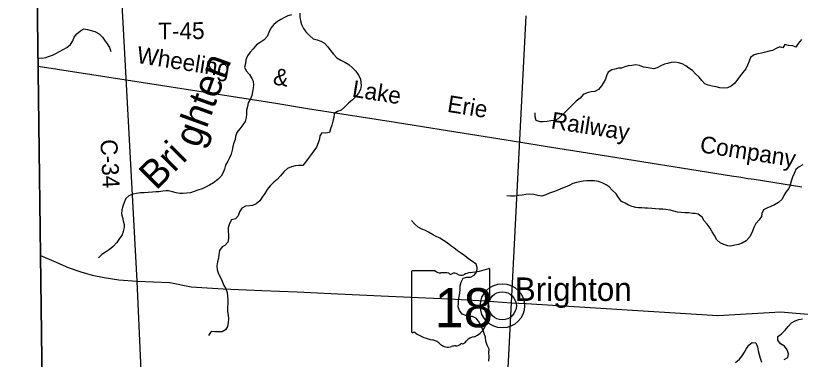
# Model space of a CAD drawing. Extents: x 1857828 to 2277390, y 930619 to 1324581.
# Drawn here: x 2012264 to 2026202, y 1154192 to 1160303 of the extents above; entities that cross this region are included whole.
import ezdxf

# ---------------------------------------------------------------- set-up
doc = ezdxf.new("R2010")
doc.units = 0
for name, color, linetype in [('GM_X_Adjacent_County', 7, 'Continuous'), ('GM_X_County', 7, 'Continuous'), ('GM_X_County_Road', 7, 'Continuous'), ('GM_X_County_Road_Text', 7, 'Continuous'), ('GM_X_Major_River', 7, 'Continuous'), ('GM_X_Minor_River', 7, 'Continuous'), ('GM_X_Minor_River_Text', 7, 'Continuous'), ('GM_X_Rail_Line', 7, 'Continuous'), ('GM_X_Rail_Line_Text', 7, 'Continuous'), ('GM_X_State_Location', 7, 'Continuous'), ('GM_X_State_Route', 7, 'Continuous'), ('GM_X_State_Shield', 7, 'Continuous'), ('GM_X_Township', 7, 'Continuous'), ('GM_X_Township_Road_Text', 7, 'Continuous'), ('GM_X_Unincorporated', 7, 'Continuous'), ('GM_X_Unincorporated_Location', 7, 'Continuous'), ('GM_X_Unincorporated_Text', 7, 'Continuous')]:
    doc.layers.add(name, color=color, linetype=linetype)

msp = doc.modelspace()

# ---------------------------------------------------------------- linework, layer by layer
at = {"layer": 'GM_X_Adjacent_County'}
msp.add_lwpolyline([(2012647, 1160718), (2012707, 1156038), (2012755, 1152350), (2012777, 1149904), (2012943, 1143096), (2013016, 1137995), (2013087, 1135030), (2013201, 1130286), (2013424, 1120950), (2013523, 1116786), (2010804, 1116774), (2007584, 1116766), (2002726, 1116787), (1997008, 1116752)], dxfattribs=at)
at = {"layer": 'GM_X_County'}
msp.add_lwpolyline([(2027656, 1116790), (2024866, 1116799), (2023245, 1116823), (2022479, 1116818), (2021874, 1116815), (2020156, 1116833), (2016220, 1116802), (2013523, 1116786), (2013424, 1120950), (2013201, 1130286), (2013087, 1135030), (2013016, 1137995), (2012943, 1143096), (2012777, 1149904), (2012755, 1152350), (2012707, 1156038), (2012647, 1160718)], dxfattribs=at)
at = {"layer": 'GM_X_County_Road'}
for points in [[(2014423, 1155583), (2014164, 1160397), (2013943, 1164756), (2013892, 1166007)], [(2014989, 1143103), (2014948, 1143924), (2014904, 1144864), (2014423, 1155583)]]:
    msp.add_lwpolyline(points, dxfattribs=at)
at = {"layer": 'GM_X_Major_River'}
for points in [[(2025913, 1154187), (2025978, 1154222), (2025993, 1154292), (2025968, 1154359), (2025921, 1154426), (2025853, 1154467), (2025800, 1154532), (2025802, 1154598), (2025869, 1154644), (2025931, 1154711), (2025988, 1154774), (2026043, 1154838), (2026112, 1154877), (2026175, 1154898), (2026243, 1154911)], [(2025048, 1154136), (2025121, 1154193), (2025171, 1154255), (2025208, 1154316), (2025245, 1154384), (2025286, 1154444), (2025347, 1154491), (2025411, 1154484), (2025440, 1154411), (2025455, 1154343), (2025474, 1154276), (2025486, 1154212), (2025513, 1154143)]]:
    msp.add_lwpolyline(points, dxfattribs=at)
at = {"layer": 'GM_X_Minor_River'}
for points in [[(2017311, 1160348), (2017314, 1160282), (2017323, 1160211), (2017339, 1160147), (2017374, 1160078), (2017421, 1160015), (2017482, 1159948), (2017548, 1159893), (2017620, 1159872), (2017684, 1159853), (2017752, 1159815), (2017809, 1159752), (2017855, 1159685), (2017910, 1159616), (2017967, 1159553), (2018037, 1159510), (2018109, 1159479), (2018179, 1159438), (2018246, 1159378), (2018306, 1159315), (2018355, 1159248), (2018390, 1159179), (2018398, 1159113), (2018399, 1159063), (2018388, 1158991), (2018355, 1158923), (2018306, 1158864), (2018247, 1158804), (2018177, 1158745), (2018106, 1158674), (2018043, 1158623), (2017980, 1158600), (2017920, 1158566), (2017913, 1158492), (2017900, 1158428), (2017879, 1158358), (2017859, 1158290), (2017838, 1158226), (2017770, 1158213), (2017702, 1158218), (2017667, 1158165), (2017660, 1158111), (2017637, 1158039), (2017610, 1157967), (2017559, 1157897), (2017515, 1157836), (2017462, 1157766), (2017415, 1157701), (2017364, 1157641), (2017292, 1157636), (2017227, 1157635), (2017161, 1157618), (2017094, 1157583), (2017027, 1157524), (2016969, 1157457), (2016908, 1157391), (2016849, 1157340), (2016786, 1157275), (2016729, 1157211), (2016688, 1157138), (2016643, 1157078), (2016601, 1157011), (2016536, 1156955), (2016472, 1156930), (2016417, 1156921), (2016349, 1156916), (2016280, 1156879), (2016241, 1156813), (2016214, 1156745), (2016171, 1156688), (2016098, 1156671), (2016061, 1156607), (2016040, 1156533), (2016041, 1156461), (2016044, 1156411), (2016047, 1156343), (2016034, 1156274)], [(2017162, 1160316), (2017101, 1160299), (2017039, 1160270), (2016976, 1160233), (2016913, 1160200), (2016850, 1160144), (2016795, 1160079), (2016760, 1160005), (2016733, 1159935), (2016679, 1159874), (2016608, 1159829), (2016541, 1159784), (2016482, 1159716), (2016431, 1159653), (2016380, 1159587), (2016355, 1159520), (2016344, 1159451), (2016331, 1159387), (2016356, 1159323), (2016416, 1159260), (2016461, 1159189), (2016482, 1159138), (2016487, 1159070), (2016483, 1159018), (2016472, 1158948), (2016459, 1158886), (2016438, 1158822), (2016393, 1158756), (2016384, 1158688), (2016367, 1158622), (2016366, 1158554), (2016357, 1158490), (2016338, 1158422), (2016297, 1158360), (2016243, 1158289), (2016194, 1158223), (2016171, 1158153), (2016160, 1158103), (2016137, 1158043), (2016122, 1157975), (2016111, 1157913), (2016092, 1157839), (2016065, 1157778), (2016030, 1157714), (2015993, 1157644), (2015974, 1157574), (2015947, 1157512), (2015912, 1157451), (2015855, 1157387), (2015780, 1157332), (2015709, 1157291), (2015646, 1157258), (2015577, 1157225), (2015502, 1157200), (2015436, 1157175), (2015371, 1157154), (2015305, 1157145), (2015236, 1157138), (2015182, 1157141), (2015116, 1157152), (2015050, 1157169), (2014980, 1157188), (2014929, 1157189), (2014879, 1157181), (2014805, 1157172), (2014752, 1157169), (2014692, 1157166), (2014619, 1157159), (2014547, 1157154), (2014479, 1157151), (2014410, 1157142), (2014344, 1157127), (2014275, 1157102), (2014220, 1157049), (2014193, 1156981), (2014168, 1156915), (2014151, 1156849), (2014146, 1156781), (2014161, 1156716), (2014174, 1156654), (2014191, 1156588), (2014191, 1156537), (2014176, 1156467), (2014153, 1156403), (2014106, 1156338), (2014060, 1156272), (2013997, 1156201), (2013930, 1156146), (2013861, 1156099), (2013796, 1156054), (2013733, 1155998)], [(2012666, 1159555), (2012733, 1159546), (2012797, 1159562), (2012848, 1159577), (2012915, 1159604), (2012979, 1159633), (2013109, 1159703), (2013174, 1159740), (2013237, 1159792), (2013280, 1159855), (2013305, 1159923), (2013350, 1159983), (2013413, 1160032), (2013468, 1160069), (2013538, 1160058), (2013606, 1160039), (2013672, 1160020), (2013746, 1159981), (2013808, 1159922), (2013853, 1159853), (2013886, 1159802), (2013932, 1159737), (2013957, 1159668)], [(2026224, 1159878), (2026166, 1159806), (2026121, 1159745), (2026067, 1159766), (2025995, 1159775), (2025929, 1159788), (2025894, 1159734), (2025840, 1159751), (2025775, 1159718), (2025710, 1159683), (2025646, 1159670), (2025583, 1159656), (2025515, 1159635), (2025450, 1159626), (2025384, 1159609), (2025319, 1159562), (2025292, 1159496), (2025261, 1159424), (2025234, 1159357), (2025182, 1159295), (2025133, 1159234), (2025086, 1159168), (2025037, 1159105), (2024974, 1159051), (2024909, 1159020), (2024845, 1159017), (2024773, 1159020), (2024706, 1159035), (2024636, 1159051), (2024568, 1159068), (2024504, 1159091), (2024451, 1159150), (2024403, 1159211), (2024342, 1159268), (2024288, 1159327)], [(2024288, 1159327), (2024221, 1159368), (2024169, 1159411), (2024103, 1159448), (2024039, 1159467), (2023975, 1159478), (2023906, 1159469), (2023840, 1159454), (2023789, 1159439), (2023725, 1159410), (2023660, 1159374), (2023597, 1159359), (2023533, 1159368), (2023465, 1159383), (2023415, 1159386), (2023347, 1159419), (2023283, 1159432), (2023212, 1159417), (2023146, 1159410), (2023083, 1159393), (2023023, 1159372), (2022972, 1159367), (2022906, 1159354), (2022855, 1159343), (2022788, 1159301), (2022759, 1159234), (2022742, 1159172), (2022697, 1159106), (2022668, 1159054), (2022617, 1158993), (2022552, 1158952), (2022486, 1158947), (2022413, 1158934), (2022347, 1158901), (2022289, 1158835), (2022218, 1158780), (2022155, 1158717), (2022025, 1158590), (2021966, 1158535), (2021908, 1158472), (2021840, 1158441), (2021771, 1158434), (2021707, 1158421), (2021630, 1158418), (2021578, 1158414), (2021512, 1158440), (2021493, 1158506), (2021492, 1158578)], [(2026249, 1157649), (2026182, 1157614), (2026123, 1157567), (2026094, 1157499), (2026061, 1157433), (2026038, 1157361), (2026021, 1157295), (2025998, 1157229), (2025947, 1157166), (2025912, 1157104), (2025879, 1157042), (2025816, 1156979), (2025745, 1156940), (2025676, 1156911), (2025609, 1156882), (2025546, 1156851), (2025521, 1156783), (2025513, 1156733), (2025469, 1156671), (2025410, 1156610), (2025379, 1156536), (2025352, 1156470), (2025327, 1156416), (2025298, 1156363), (2025243, 1156299), (2025170, 1156258), (2025106, 1156235), (2025037, 1156220), (2024965, 1156207), (2024912, 1156210), (2024846, 1156231), (2024778, 1156262), (2024721, 1156317), (2024676, 1156392), (2024638, 1156459), (2024599, 1156524), (2024546, 1156593), (2024492, 1156652)], [(2024492, 1156652), (2024457, 1156719), (2024387, 1156776), (2024337, 1156783), (2024287, 1156788), (2024221, 1156795), (2024151, 1156798), (2024084, 1156803), (2024018, 1156810), (2023954, 1156827), (2023888, 1156846), (2023816, 1156855), (2023761, 1156860), (2023693, 1156865), (2023629, 1156870), (2023563, 1156875), (2023490, 1156880), (2023438, 1156881), (2023388, 1156883), (2023330, 1156886), (2023278, 1156893), (2023215, 1156910), (2023151, 1156933), (2023092, 1156966), (2023024, 1157001), (2022972, 1157072), (2022933, 1157137), (2022862, 1157201), (2022806, 1157260), (2022754, 1157295), (2022683, 1157328), (2022615, 1157357), (2022548, 1157366), (2022480, 1157365), (2022414, 1157364), (2022347, 1157361), (2022285, 1157350), (2022224, 1157335), (2022160, 1157316), (2022093, 1157285), (2022026, 1157255), (2021947, 1157222), (2021883, 1157193), (2021816, 1157172), (2021747, 1157147), (2021681, 1157118), (2021608, 1157095), (2021540, 1157104), (2021470, 1157125), (2021399, 1157130), (2021329, 1157125), (2021260, 1157112), (2021194, 1157103), (2021123, 1157096), (2021053, 1157094), (2020987, 1157097)], [(2019541, 1156482), (2019477, 1156509), (2019413, 1156542), (2019350, 1156599), (2019296, 1156658)], [(2020667, 1154160), (2020676, 1154233), (2020671, 1154305), (2020674, 1154375), (2020638, 1154446), (2020617, 1154517), (2020610, 1154585), (2020585, 1154652), (2020560, 1154720), (2020529, 1154789), (2020495, 1154854), (2020448, 1154917), (2020376, 1154956), (2020326, 1154953), (2020260, 1154970), (2020196, 1154995), (2020146, 1155062), (2020125, 1155126), (2020130, 1155192), (2020131, 1155243), (2020142, 1155309), (2020155, 1155371), (2020158, 1155437), (2020161, 1155501), (2020180, 1155565), (2020211, 1155633), (2020281, 1155650), (2020342, 1155655), (2020408, 1155686), (2020457, 1155748), (2020462, 1155822), (2020441, 1155884), (2020380, 1155929), (2020314, 1155975), (2020240, 1156032), (2020185, 1156071), (2020115, 1156122), (2020047, 1156173), (2019995, 1156210), (2019928, 1156263), (2019862, 1156303), (2019796, 1156346), (2019722, 1156381), (2019667, 1156414), (2019595, 1156455), (2019541, 1156482)], [(2016034, 1156274), (2015981, 1156215), (2015929, 1156190), (2015884, 1156126), (2015873, 1156058), (2015866, 1155990), (2015851, 1155924), (2015836, 1155856), (2015845, 1155784), (2015866, 1155715), (2015903, 1155648), (2015934, 1155583), (2015958, 1155515), (2015995, 1155448), (2016018, 1155381), (2016027, 1155315), (2016034, 1155245), (2016031, 1155184), (2016028, 1155114), (2016029, 1155040), (2016038, 1154978), (2016042, 1154911), (2016041, 1154843), (2016026, 1154777), (2015991, 1154715), (2015932, 1154678), (2015868, 1154679), (2015799, 1154682), (2015735, 1154687), (2015688, 1154618)]]:
    msp.add_lwpolyline(points, dxfattribs=at)
at = {"layer": 'GM_X_Rail_Line'}
msp.add_lwpolyline([(2012664, 1159404), (2014837, 1159067), (2016849, 1158751), (2017446, 1158655), (2018057, 1158558), (2019008, 1158408), (2019823, 1158278), (2021238, 1158053), (2021670, 1157984), (2022535, 1157846), (2024981, 1157456), (2025112, 1157435), (2025276, 1157410), (2025382, 1157393), (2026230, 1157257)], dxfattribs=at)
at = {"layer": 'GM_X_State_Route'}
for points in [[(2020855, 1150903), (2020855, 1150903), (2021073, 1155198), (2021331, 1160303)], [(2012707, 1156038), (2012939, 1155936), (2013195, 1155822), (2013424, 1155748), (2013622, 1155687), (2013836, 1155644), (2014095, 1155603), (2014423, 1155583), (2015003, 1155555), (2015380, 1155479), (2015949, 1155446), (2016634, 1155416), (2017265, 1155390), (2017985, 1155356), (2018758, 1155323), (2019413, 1155293), (2019968, 1155266), (2020589, 1155234), (2021073, 1155198), (2021335, 1155182)], [(2021335, 1155182), (2021335, 1155182), (2024739, 1154971), (2025850, 1155035), (2028500, 1154813), (2028501, 1154813)]]:
    msp.add_lwpolyline(points, dxfattribs=at)
at = {"layer": 'GM_X_State_Shield'}
for p, q in [((2019293, 1155744), (2019293, 1154688)), ((2019714, 1155763), (2019307, 1155763)), ((2020685, 1155236), (2020685, 1155789)), ((2020685, 1155236), (2020685, 1155236))]:
    msp.add_line(p, q, dxfattribs=at)
for centre, radius, start, end in [((2019309, 1155747), 16.1, 98.1301, 188.1301), ((2019812, 1155885), 156, 231.6195, 271.1119), ((2020189, 1157203), 1476, 275.8445, 288.9065), ((2020670, 1155791), 15.5, 351.8621, 97.738), ((2019863, 1155169), 562, 80.4867, 94.9883), ((2019991, 1155752), 45.1, 219.7921, 297.1024), ((2020057, 1155630), 93.8, 54.4667, 119.1411), ((2020178, 1155798), 113, 233.8562, 294.8282), ((2020378, 1155440), 297, 97.3462, 120.7689), ((2020682, 1155196), 24, 107.944, 210.337), ((2020529, 1155126), 144, 340.033, 23.6496), ((2020669, 1155234), 16.6, 289.6038, 7.7341), ((2020741, 1155005), 105, 136.8065, 186.9296), ((2020272, 1154934), 369, 292.3089, 8.9858), ((2019309, 1154686), 16.3, 171.9584, 258.3066), ((2019312, 1154794), 124, 267.339, 280.6039), ((2019337, 1154627), 44.8, 29.7484, 93.2717), ((2019902, 1155576), 1066, 240.4129, 257.1985), ((2019584, 1154213), 334, 47.1842, 75.836), ((2020171, 1154585), 119, 282.8732, 323.2771), ((2020428, 1154391), 202, 94.4031, 142.5768), ((2019945, 1154622), 212, 230.7004, 286.2918), ((2020068, 1154256), 174, 85.6951, 111.2099), ((2020083, 1154543), 113, 268.777, 315.5493), ((2020185, 1154440), 31.8, 65.7517, 132.6484)]:
    msp.add_arc(centre, radius, start, end, dxfattribs=at)
at = {"layer": 'GM_X_Township'}
msp.add_lwpolyline([(2012531, 1166018), (2013892, 1166008), (2017576, 1165980), (2021617, 1165950), (2028230, 1165900), (2032206, 1165870), (2032202, 1162261), (2032191, 1160469), (2032191, 1160394), (2032187, 1160189), (2032188, 1160111), (2032164, 1154605), (2032103, 1147063), (2032060, 1143020), (2026094, 1143049), (2021395, 1143072), (2014989, 1143103), (2012943, 1143096), (2012777, 1149904), (2012755, 1152350), (2012707, 1156038), (2012647, 1160718), (2012559, 1164716)], close=True, dxfattribs=at)
at = {"layer": 'GM_X_Unincorporated'}
for radius in [393, 249]:
    msp.add_circle((2020909, 1155143), radius, dxfattribs=at)
at = {"layer": 'GM_X_Unincorporated_Location'}
msp.add_line((2020909, 1155143), (2020909, 1155143), dxfattribs=at)

# ---------------------------------------------------------------- texts
at = {"layer": 'GM_X_County_Road_Text'}
msp.add_text('C-34', height=300, rotation=273.1043, dxfattribs=at).set_placement((2013767, 1158097))
at = {"layer": 'GM_X_Minor_River_Text'}
for s, rotation, p in [('ghten', 69.9932, (2015528, 1157935)), ('Bri', 44.9927, (2014761, 1157185))]:
    msp.add_text(s, height=500.2, rotation=rotation, dxfattribs=at).set_placement(p)
at = {"layer": 'GM_X_Rail_Line_Text'}
for s, rotation, p in [('Wheeling', 351.0617, (2014400, 1159466)), ('&', 351.309, (2016824, 1159081)), ('Lake', 350.9199, (2018228, 1158863)), ('Erie', 350.9456, (2019918, 1158595)), ('Railway', 350.9955, (2021761, 1158300)), ('Company', 351.0133, (2024405, 1157876))]:
    msp.add_text(s, height=299, rotation=rotation, dxfattribs=at).set_placement(p)
at = {"layer": 'GM_X_State_Location'}
msp.add_text('18', height=1, rotation=0, dxfattribs=at).set_placement((2019722, 1155073))
for s in ['s', 'r']:
    msp.add_text(s, height=1, dxfattribs=at).set_placement((2019973, 1155146))
at = {"layer": 'GM_X_State_Shield'}
msp.add_text('18', height=696.1, dxfattribs=at).set_placement((2019705, 1154762))
at = {"layer": 'GM_X_Township_Road_Text'}
msp.add_text('T-45', height=300, rotation=0.7069, dxfattribs=at).set_placement((2014796, 1159879))
at = {"layer": 'GM_X_Unincorporated_Text'}
msp.add_text('Brighton', height=417, rotation=0, dxfattribs=at).set_placement((2021130, 1155230))

doc.saveas('drawing.dxf')
